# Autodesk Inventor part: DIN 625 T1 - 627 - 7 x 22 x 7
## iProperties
Author: Philippe
Created: 2002-08
Part Number: DIN 625 T1 - 627 - 7 x 22 x 7
Material: Par défaut
Catalog Web Link: file:///C:/Program Files/Autodesk/Inventor 5/Content/Din/index.htm?doNavigateId=4AD379DC-10FA-4853-8ADA-6A4A7C43E350|722B25F4B16B11D4BA6900C04F798F98|true
Description: Roulement rainuré à billes
Document SubType Name: Standard Catalog Part
Standard: DIN 625 T1 - 627 - 7 x 22 x 7
Designer: Philippe
CLASSIFICATION: 31171504 un/spsc
MANUFACTURER: DIN Système de normes
Control State: 0
Master: False
Checked Out: False
PropertySet Name: Design Tracking Control
Shininess: 20.0
Angle Display Precision: 2
Document Length Units: 11269
Document Angle Units: 11283
Document Time Units: 11279
Document Mass Units: 11290
Document Length Units Precision: 3
Document Angle Units Precision: 2
Compacted: False
PropertySet Name: _Private Model Information
Density: 0.0
Volumn: 0.0
Area: 0.0
PropertySet Name: Model Information
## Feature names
1. Base1
